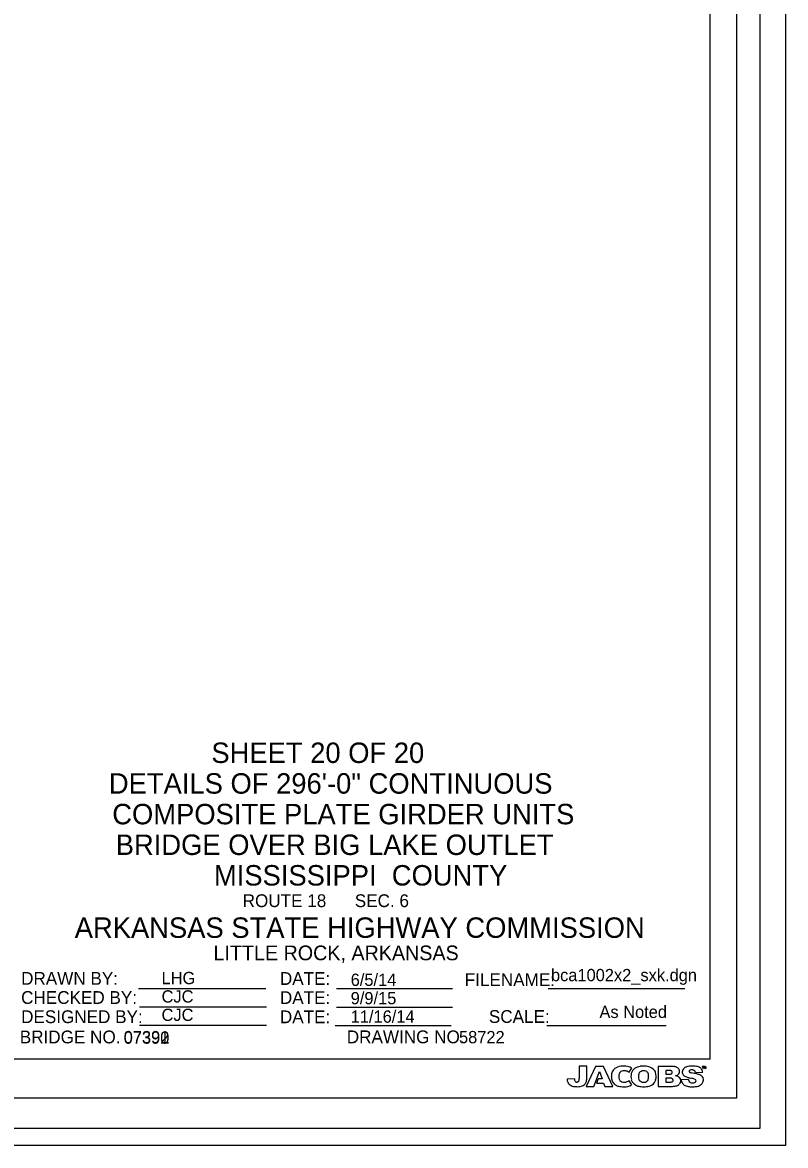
# Model space of a CAD drawing. Extents: x -1771525.9 to -1771483.9, y -422628.9 to -422606.9.
# Drawn here: x -1771498.88 to -1771491.42, y -422628.88 to -422617.89 of the extents above; entities that cross this region are included whole.
import ezdxf

# ---------------------------------------------------------------- set-up
doc = ezdxf.new("R2010")
doc.units = 0
for name, color, linetype in [('border', 7, 'Continuous'), ('Border 2660-Hwy18 - Level 62', 7, 'Continuous'), ('Border 2660-Hwy18 - Level 63', 7, 'Continuous'), ('Border 2660-Hwy18 - Text', 7, 'Continuous'), ('Border 2660-Hwy18 - Title Text', 7, 'Continuous'), ('Bridge No BLFR', 7, 'Continuous'), ('Bridge No BLO', 7, 'Continuous'), ('Bridge No Ditch 81', 7, 'Continuous'), ('Level 62 PDF', 7, 'Continuous'), ('Text', 7, 'Continuous'), ('Title Block Text', 7, 'Continuous'), ('Title Text', 7, 'Continuous')]:
    doc.layers.add(name, color=color, linetype=linetype)

msp = doc.modelspace()

# ---------------------------------------------------------------- linework, layer by layer
at = {"layer": 'border'}
for p, q in [((-1771492.157, -422628.038), (-1771492.157, -422607.492)), ((-1771497.744, -422627.346), (-1771496.501, -422627.346)), ((-1771495.811, -422627.348), (-1771494.677, -422627.348)), ((-1771493.741, -422627.348), (-1771492.405, -422627.348)), ((-1771497.737, -422627.526), (-1771496.494, -422627.526)), ((-1771495.811, -422627.528), (-1771494.677, -422627.528)), ((-1771497.737, -422627.706), (-1771496.494, -422627.706)), ((-1771495.822, -422627.708), (-1771494.688, -422627.708)), ((-1771493.754, -422627.708), (-1771492.588, -422627.708)), ((-1771492.157, -422628.038), (-1771524.168, -422628.038))]:
    msp.add_line(p, q, dxfattribs=at)
for points in [[(-1771493.362, -422628.217), (-1771493.362, -422628.107), (-1771493.437, -422628.107), (-1771493.437, -422628.228)], [(-1771493.24, -422628.16), (-1771493.214, -422628.23), (-1771493.252, -422628.23), (-1771493.268, -422628.273), (-1771493.198, -422628.273), (-1771493.186, -422628.305), (-1771493.109, -422628.305), (-1771493.198, -422628.109), (-1771493.279, -422628.109), (-1771493.369, -422628.305), (-1771493.293, -422628.305), (-1771493.24, -422628.16)], [(-1771492.523, -422628.109), (-1771492.665, -422628.109), (-1771492.665, -422628.305)], [(-1771492.558, -422628.149), (-1771492.591, -422628.149), (-1771492.591, -422628.186)], [(-1771492.3, -422628.167), (-1771492.23, -422628.164)], [(-1771492.219, -422628.111), (-1771492.234, -422628.111), (-1771492.234, -422628.113), (-1771492.228, -422628.113), (-1771492.228, -422628.13), (-1771492.225, -422628.13), (-1771492.225, -422628.113), (-1771492.219, -422628.113), (-1771492.219, -422628.111)], [(-1771492.214, -422628.114), (-1771492.214, -422628.114), (-1771492.208, -422628.13), (-1771492.206, -422628.13), (-1771492.2, -422628.114), (-1771492.2, -422628.114), (-1771492.2, -422628.13), (-1771492.198, -422628.13), (-1771492.198, -422628.111), (-1771492.201, -422628.111), (-1771492.207, -422628.127), (-1771492.213, -422628.111), (-1771492.217, -422628.111), (-1771492.217, -422628.13), (-1771492.214, -422628.13), (-1771492.214, -422628.114)], [(-1771493.484, -422628.229), (-1771493.555, -422628.232)], [(-1771492.591, -422628.186), (-1771492.557, -422628.186)], [(-1771492.554, -422628.223), (-1771492.591, -422628.223), (-1771492.591, -422628.263)], [(-1771492.591, -422628.263), (-1771492.553, -422628.263)], [(-1771492.369, -422628.237), (-1771492.439, -422628.24)], [(-1771492.665, -422628.305), (-1771492.538, -422628.305)]]:
    msp.add_lwpolyline(points, dxfattribs=at)
for centre, radius, start, end in [((-1771493.024, -422628.202), 0.0987, 155.2444, 178.6811), ((-1771493.04, -422628.194), 0.0809, 126.8513, 155.2444), ((-1771493.021, -422628.221), 0.114, 94.7853, 126.8513), ((-1771492.946, -422628.209), 0.104, 161.2834, 178.6702), ((-1771493.021, -422628.184), 0.0243, 134.3139, 161.2834), ((-1771492.999, -422628.206), 0.0556, 110.7655, 134.3139), ((-1771493, -422628.469), 0.363, 86.903, 94.7853), ((-1771493, -422628.204), 0.0529, 91.5073, 110.7655), ((-1771492.998, -422628.267), 0.116, 82.6359, 91.5073), ((-1771492.99, -422628.201), 0.0493, 65.5548, 82.6359), ((-1771492.986, -422628.219), 0.113, 56.9246, 86.903), ((-1771493.019, -422628.264), 0.119, 54.6002, 65.5548), ((-1771492.7, -422628.284), 0.276, 144.635, 154.8844), ((-1771492.831, -422628.205), 0.1, 148.6249, 181.2859), ((-1771492.853, -422628.192), 0.0755, 123.8806, 148.6249), ((-1771492.816, -422628.247), 0.142, 111.7104, 123.8806), ((-1771492.828, -422628.217), 0.109, 96.5371, 111.7104), ((-1771492.766, -422628.207), 0.0917, 160.8611, 181.2981), ((-1771492.826, -422628.186), 0.0287, 136.1177, 160.8611), ((-1771492.809, -422628.203), 0.0518, 117.7176, 136.1177), ((-1771492.796, -422628.489), 0.384, 91.9058, 96.5371), ((-1771492.815, -422628.191), 0.0382, 100.2108, 117.7176), ((-1771492.806, -422628.241), 0.0895, 90.9675, 100.2108), ((-1771492.802, -422628.271), 0.166, 73.4477, 92.4253), ((-1771492.807, -422628.214), 0.0622, 67.077, 90.4218), ((-1771492.798, -422628.192), 0.0386, 24.6274, 67.077), ((-1771492.814, -422628.199), 0.056, 2.7442, 24.6274), ((-1771492.787, -422628.22), 0.112, 41.1934, 73.4477), ((-1771492.746, -422628.184), 0.0579, 18.6966, 41.1934), ((-1771492.815, -422628.207), 0.13, 344.5708, 18.6966), ((-1771492.56, -422628.284), 0.135, 86.2098, 89.3498), ((-1771492.554, -422628.2), 0.0514, 74.8723, 86.2098), ((-1771492.546, -422628.169), 0.0196, 40.2425, 74.8723), ((-1771492.546, -422628.165), 0.0196, 284.1438, 307.8865), ((-1771492.543, -422628.168), 0.0149, 307.8866, 341.4625), ((-1771492.539, -422628.164), 0.0108, 21.9604, 40.2425), ((-1771492.547, -422628.167), 0.0195, 341.4625, 21.9604), ((-1771492.523, -422628.213), 0.104, 72.1885, 90.1477), ((-1771492.51, -422628.171), 0.0603, 61.4844, 72.1885), ((-1771492.508, -422628.168), 0.0564, 34.7868, 61.4844), ((-1771492.501, -422628.153), 0.0471, 296.8412, 329.8182), ((-1771492.488, -422628.154), 0.0315, 16.9455, 34.7868), ((-1771492.487, -422628.161), 0.0307, 329.8182, 347.0949), ((-1771492.501, -422628.158), 0.0455, 347.0949, 16.9455), ((-1771492.383, -422628.164), 0.0476, 124.08, 177.6485), ((-1771492.389, -422628.164), 0.0416, 177.6485, 218.8535), ((-1771492.352, -422628.21), 0.103, 108.2808, 124.08), ((-1771492.359, -422628.189), 0.0811, 99.8173, 108.2808), ((-1771492.331, -422628.348), 0.242, 93.402, 99.8173), ((-1771492.354, -422628.157), 0.00815, 165.3108, 208.2887), ((-1771492.347, -422628.159), 0.016, 146.4706, 165.3108), ((-1771492.347, -422628.152), 0.0169, 211.7417, 226.6339), ((-1771492.353, -422628.155), 0.00877, 130.7855, 146.4706), ((-1771492.342, -422628.168), 0.0256, 97.3055, 130.7855), ((-1771492.349, -422628.154), 0.0145, 226.6339, 245.1429), ((-1771492.332, -422628.117), 0.0549, 245.1429, 260.9806), ((-1771492.331, -422628.359), 0.254, 80.6549, 93.402), ((-1771492.336, -422628.211), 0.0692, 81.3212, 97.3055), ((-1771492.416, -422628.645), 0.479, 77.5139, 80.9806), ((-1771492.331, -422628.178), 0.0359, 57.474, 81.3212), ((-1771492.323, -422628.165), 0.0202, 37.1977, 57.474), ((-1771492.739, -422630.107), 1.977, 76.8035, 77.5139), ((-1771492.335, -422628.174), 0.0351, 11.0051, 37.1977), ((-1771492.304, -422628.197), 0.0897, 57.5906, 80.6549), ((-1771492.282, -422628.163), 0.0494, 39.0736, 57.5906), ((-1771492.292, -422628.171), 0.0612, 6.4385, 39.0736), ((-1771493.433, -422628.223), 0.123, 184.5698, 198.1069), ((-1771493.499, -422628.244), 0.0527, 198.1069, 225.9799), ((-1771493.481, -422628.225), 0.0797, 225.9799, 261.0714), ((-1771493.424, -422628.231), 0.0602, 178.2556, 191.4961), ((-1771493.456, -422628.237), 0.0277, 191.4961, 218.7511), ((-1771493.464, -422628.244), 0.0164, 218.7511, 257.488), ((-1771493.46, -422628.227), 0.0345, 257.488, 275.7834), ((-1771493.46, -422628.235), 0.0257, 275.7834, 301.6926), ((-1771493.452, -422628.247), 0.0122, 301.6926, 325.4171), ((-1771493.466, -422628.238), 0.0285, 325.4171, 349.1575), ((-1771493.516, -422628.228), 0.0792, 349.1575, 360), ((-1771493.443, -422628.213), 0.0931, 279.1616, 305.8646), ((-1771493.423, -422628.241), 0.0585, 305.8646, 338.7843), ((-1771493.418, -422628.243), 0.0527, 338.7843, 350.0951), ((-1771493.907, -422628.157), 0.549, 350.0951, 351.3706), ((-1771493.486, -422628.221), 0.124, 351.3706, 1.8291), ((-1771492.97, -422628.203), 0.153, 178.6811, 194.3912), ((-1771493.062, -422628.227), 0.0582, 194.3912, 214.1799), ((-1771493.005, -422628.188), 0.127, 214.1799, 231.6615), ((-1771493.036, -422628.228), 0.0765, 231.6616, 258.686), ((-1771492.964, -422628.209), 0.0855, 178.6702, 195.8531), ((-1771493.006, -422628.221), 0.0421, 195.8531, 214.5369), ((-1771493.008, -422628.223), 0.0388, 214.5369, 253.1918), ((-1771492.997, -422628.186), 0.0769, 253.1918, 291.1956), ((-1771492.996, -422628.163), 0.146, 268.8163, 299.3878), ((-1771493.003, -422628.171), 0.0928, 291.1956, 305.5144), ((-1771492.586, -422628.064), 0.407, 206.7197, 213.678), ((-1771492.779, -422628.203), 0.152, 181.2859, 193.1956), ((-1771492.861, -422628.223), 0.0683, 193.1956, 217.7499), ((-1771492.828, -422628.196), 0.111, 217.7499, 244.1703), ((-1771492.763, -422628.207), 0.0951, 181.2981, 197.9492), ((-1771492.825, -422628.227), 0.0299, 197.9492, 222.7741), ((-1771492.812, -422628.215), 0.0474, 222.7741, 250.1955), ((-1771492.811, -422628.212), 0.0507, 250.1955, 269.1264), ((-1771492.809, -422628.072), 0.191, 269.1264, 272.0424), ((-1771492.804, -422628.212), 0.0512, 272.0424, 299.5401), ((-1771492.796, -422628.225), 0.036, 299.5401, 342.4003), ((-1771492.849, -422628.208), 0.091, 342.4003, 0.0845), ((-1771493.007, -422628.208), 0.249, 0.0845, 2.7442), ((-1771492.781, -422628.205), 0.101, 285.9017, 322.6714), ((-1771492.756, -422628.223), 0.0698, 322.6714, 344.5708), ((-1771492.557, -422628.122), 0.0633, 270.0363, 284.1438), ((-1771492.558, -422628.47), 0.247, 86.6838, 88.8756), ((-1771492.553, -422628.159), 0.104, 270.0001, 276.6749), ((-1771492.547, -422628.273), 0.0497, 75.9314, 86.6838), ((-1771492.546, -422628.219), 0.043, 276.6749, 293.0645), ((-1771492.543, -422628.257), 0.0328, 59.6202, 75.9314), ((-1771492.536, -422628.243), 0.0178, 293.0645, 337.5037), ((-1771492.534, -422628.241), 0.015, 30.8341, 59.6202), ((-1771492.536, -422628.243), 0.0177, 337.5037, 30.8341), ((-1771492.514, -422628.128), 0.0753, 284.6785, 296.8411), ((-1771492.511, -422628.291), 0.092, 61.0815, 79.9242), ((-1771492.502, -422628.24), 0.0609, 279.6279, 313.6357), ((-1771492.485, -422628.245), 0.039, 44.9773, 61.0815), ((-1771492.495, -422628.247), 0.0511, 313.6357, 342.9845), ((-1771492.489, -422628.249), 0.0452, 342.9845, 44.9773), ((-1771492.063, -422628.187), 0.38, 187.9971, 189.0947), ((-1771492.389, -422628.239), 0.0503, 189.0947, 202.464), ((-1771492.354, -422628.225), 0.0881, 202.464, 215.8926), ((-1771492.375, -422628.24), 0.0621, 215.8926, 243.2968), ((-1771492.377, -422628.154), 0.0566, 218.8535, 233.6549), ((-1771492.364, -422628.136), 0.0797, 233.6549, 244.7689), ((-1771492.331, -422628.066), 0.156, 244.7689, 253.473), ((-1771492.284, -422627.906), 0.323, 253.473, 259.8297), ((-1771492.318, -422628.229), 0.0523, 188.5141, 201.638), ((-1771492.337, -422628.236), 0.0319, 201.638, 242.3635), ((-1771492.331, -422628.225), 0.045, 242.3635, 264.6229), ((-1771492.393, -422628.517), 0.297, 76.0104, 79.8297), ((-1771492.327, -422628.189), 0.0806, 264.6229, 273.901), ((-1771492.325, -422628.223), 0.0464, 273.901, 289.1925), ((-1771492.345, -422628.323), 0.0974, 67.9593, 76.0104), ((-1771492.318, -422628.242), 0.0263, 289.1925, 322.566), ((-1771492.318, -422628.258), 0.0265, 39.9313, 67.9593), ((-1771492.309, -422628.25), 0.0145, 2.1813, 39.9313), ((-1771492.309, -422628.25), 0.0141, 322.566, 2.1813), ((-1771492.325, -422628.341), 0.163, 65.6998, 76.8035), ((-1771492.295, -422628.226), 0.0772, 295.6144, 314.022), ((-1771492.29, -422628.263), 0.0776, 51.3565, 65.6998), ((-1771492.274, -422628.243), 0.0523, 36.5162, 51.3565), ((-1771492.283, -422628.238), 0.0608, 314.022, 345.1611), ((-1771492.271, -422628.241), 0.0486, 345.1611, 36.5162), ((-1771493.455, -422628.063), 0.244, 261.0714, 269.9405), ((-1771493.455, -422628.14), 0.167, 269.9405, 279.1616), ((-1771492.993, -422628.01), 0.298, 258.686, 268.8163), ((-1771492.838, -422628.219), 0.0859, 244.1703, 259.4942), ((-1771492.8, -422628.009), 0.299, 259.4942, 268.6426), ((-1771492.802, -422628.128), 0.18, 268.6426, 285.9017), ((-1771492.548, -422627.967), 0.338, 271.7224, 279.6279), ((-1771492.362, -422628.215), 0.0904, 243.2968, 257.4598), ((-1771492.336, -422628.095), 0.213, 257.4598, 268.8656), ((-1771492.328, -422627.727), 0.581, 268.8656, 270.7612), ((-1771492.323, -422628.131), 0.177, 270.7612, 282.5001), ((-1771492.308, -422628.198), 0.109, 282.5001, 295.6144)]:
    msp.add_arc(centre, radius, start, end, dxfattribs=at)
at = {"layer": 'Border 2660-Hwy18 - Level 62'}
msp.add_lwpolyline([(-1771525.789, -422606.907), (-1771491.67, -422606.907), (-1771491.67, -422628.716), (-1771525.789, -422628.716)], close=True, dxfattribs=at)
at = {"layer": 'Border 2660-Hwy18 - Level 63'}
msp.add_lwpolyline([(-1771525.9, -422607.05), (-1771491.9, -422607.05), (-1771491.9, -422628.419), (-1771525.9, -422628.419)], close=True, dxfattribs=at)
at = {"layer": 'Level 62 PDF'}
msp.add_lwpolyline([(-1771525.539, -422607.073), (-1771491.42, -422607.073), (-1771491.42, -422628.883), (-1771525.539, -422628.883)], close=True, dxfattribs=at)

# ---------------------------------------------------------------- texts
at = {"layer": 'Border 2660-Hwy18 - Text'}
for s, p in [('DRAWN BY:', (-1771498.893, -422627.31)), ('DATE:', (-1771496.363, -422627.311)), ('FILENAME:', (-1771494.556, -422627.323)), ('CHECKED BY:', (-1771498.893, -422627.497)), ('DATE:', (-1771496.363, -422627.498)), ('DESIGNED BY:', (-1771498.893, -422627.685)), ('DATE:', (-1771496.363, -422627.686)), ('SCALE:', (-1771494.32, -422627.683)), ('BRIDGE NO.', (-1771498.906, -422627.883)), ('DRAWING NO.', (-1771495.709, -422627.882))]:
    msp.add_text(s, height=0.125, dxfattribs=at).set_placement(p)
at = {"layer": 'Border 2660-Hwy18 - Title Text'}
for s, height, p in [('MISSISSIPPI  COUNTY', 0.2, (-1771497.008, -422626.339)), ('ROUTE 18      SEC. 6', 0.125, (-1771496.727, -422626.55)), ('ARKANSAS STATE HIGHWAY COMMISSION', 0.2, (-1771498.369, -422626.851)), ('LITTLE ROCK, ARKANSAS', 0.144, (-1771497.012, -422627.07))]:
    msp.add_text(s, height=height, dxfattribs=at).set_placement(p)
at = {"layer": 'Bridge No BLFR'}
msp.add_text('07392', height=0.12, dxfattribs=at).set_placement((-1771497.89, -422627.887))
at = {"layer": 'Bridge No BLO'}
msp.add_text('07391', height=0.12, dxfattribs=at).set_placement((-1771497.89, -422627.882))
at = {"layer": 'Bridge No Ditch 81'}
msp.add_text('07390', height=0.12, dxfattribs=at).set_placement((-1771497.89, -422627.887))
at = {"layer": 'Text'}
for s, p in [('LHG', (-1771497.52, -422627.304)), ('6/5/14', (-1771495.671, -422627.321)), ('CJC', (-1771497.52, -422627.484)), ('9/9/15', (-1771495.671, -422627.501)), ('As Noted', (-1771493.239, -422627.635)), ('CJC', (-1771497.52, -422627.664)), ('11/16/14', (-1771495.671, -422627.681))]:
    msp.add_text(s, height=0.12, dxfattribs=at).set_placement(p)
at = {"layer": 'Title Block Text'}
for s, p in [('bca1002x2_sxk.dgn', (-1771493.713, -422627.275)), ('58722', (-1771494.612, -422627.882))]:
    msp.add_text(s, height=0.12, dxfattribs=at).set_placement(p)
at = {"layer": 'Title Text'}
for s, p in [('SHEET 20 OF 20', (-1771497.033, -422625.14)), ('DETAILS OF 296\'-0" CONTINUOUS', (-1771498.035, -422625.44)), ('COMPOSITE PLATE GIRDER UNITS', (-1771498.002, -422625.74)), ('BRIDGE OVER BIG LAKE OUTLET', (-1771497.968, -422626.04))]:
    msp.add_text(s, height=0.2, dxfattribs=at).set_placement(p)

doc.saveas('drawing.dxf')
